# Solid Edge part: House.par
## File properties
Title: House
Author: windows
Template: Iso Metric Part.par
Last saved by: windows
Revision: 7
Application: Solid Edge
Username: windows
Density: 886,000 kg/m^3
Accuracy: 0,990
Material: Polyethylene, low density
Face Style: Blue
Fill Style: ANSI34(Plastic)
Virtual Style: ANSI34(Plastic)
Grouping: Non-metals\Plastics
LibraryName: Materials
Coef. of Thermal Exp: 0.00016
Thermal Conductivity: 3.9
Specific Heat: 2219.0
Modulus of Elasticity: 144789897.0
Poisson's Ratio: 0.35
Yield Stress: 9652659.8
Ultimate Stress: 0.0
Elongation: 0.0
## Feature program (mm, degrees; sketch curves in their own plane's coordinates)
sketch for "unnamed Protrusion 1" plane through (0, 0, 0) normal (0, 0, 1) x-axis (1, 0, 0)
  line (-25, -25) -> (25, -25)
  line (25, -25) -> (25, 25)
  line (25, 25) -> (-25, 25)
  line (-25, 25) -> (-25, -25)
extrude "unnamed Protrusion 1" add finite 50 along +normal
draft "Draft_1"  Angles1 = 10 deg
thinwall "Thinwall_1"  Thickness = 3 mm
chamfer "Chamfer_1" setback 1
sketch for "ExtrudedCutout_1" plane through (0, -20.5918, 25) normal (0, -0.984808, 0.173648) x-axis (1, 0, 0)
  line (12.5, -11.1363) -> (12.5, 13.8637)
  line (12.5, 13.8637) -> (-12.5, 13.8637)
  line (-12.5, 13.8637) -> (-12.5, -11.1363)
  line (-12.5, -11.1363) -> (12.5, -11.1363)
extrude "ExtrudedCutout_1" cut finite 3 along -normal
sketch for "ExtrudedCutout_2" plane through (20.5918, 0, 25) normal (0.984808, 0, 0.173648) x-axis (0, 1, 0)
  line (-12.4342, 5.6895) -> (-2.4342, 5.6895)
  line (-2.4342, 5.6895) -> (-2.4342, 15.6895)
  line (-2.4342, 15.6895) -> (-12.4342, 15.6895)
  line (-12.4342, 15.6895) -> (-12.4342, 5.6895)
extrude "ExtrudedCutout_2" cut finite 3 along -normal
pattern "unnamed Pattern 1" of "ExtrudedCutout_2"
pattern "unnamed Pattern 2"
sketch for "ExtrudedCutout_3" plane through (-20.5918, 0, 25) normal (-0.984808, 0, 0.173648) x-axis (0, -1, 0)
  line (10, 9.4133) -> (-10, 9.4133)
  line (-10, 9.4133) -> (-10, -20.5867)
  line (-10, -20.5867) -> (10, -20.5867)
  line (10, -20.5867) -> (10, 9.4133)
extrude "ExtrudedCutout_3" cut finite 3 along -normal
mirror "unnamed Mirror 1" of "ExtrudedCutout_1"
pattern "unnamed Pattern 3"
sketch for "ExtrudedProtrusion_2" plane through (0, 0, 50) normal (0, 0, 1) x-axis (0, 1, 0)
  line (-35, -35) -> (35, -35)
  line (35, -35) -> (35, 35)
  line (35, 35) -> (-35, 35)
  line (-35, 35) -> (-35, -35)
extrude "ExtrudedProtrusion_2" add finite 40 along +normal
draft "Draft_2"  Angles1 = 40 deg
thinwall "Thinwall_2"  Thickness = 1 mm
sketch for "ExtrudedCutout_4" plane through (0, -18.218, 70) normal (0, -0.766044, 0.642788) x-axis (1, 0, 0)
  line (10, -15.8362) -> (10, 4.1638)
  line (10, 4.1638) -> (-10, 4.1638)
  line (-10, 4.1638) -> (-10, -15.8362)
  line (-10, -15.8362) -> (10, -15.8362)
extrude "ExtrudedCutout_4" cut finite 3 along -normal
fillet "Round_1" radius 5
fillet "Round_2" radius 1
logasc func "Lip_1"  LipOrGrooveWidth = 1.5 mm; LipOrGrooveHeight = 1.5 mm
mirror "unnamed Mirror 2" of "Lip_1" about plane through (0, 0, 0) normal (0, -1, 0)
logasc func "unnamed LOGAscFunc 1"
logasc func "Lip_2"  LipOrGrooveWidth = 1.5 mm; LipOrGrooveHeight = 1.5 mm
logasc func "Lip_3"  LipOrGrooveWidth = 1 mm; LipOrGrooveHeight = 1 mm
logasc func "Lip_4"  LipOrGrooveWidth = 1 mm; LipOrGrooveHeight = 1 mm
logasc func "Lip_5"  LipOrGrooveWidth = 1 mm; LipOrGrooveHeight = 1 mm
logasc func "Lip_6"  LipOrGrooveWidth = 1 mm; LipOrGrooveHeight = 1 mm
logasc func "Lip_7"  LipOrGrooveWidth = 1.5 mm; LipOrGrooveHeight = 1.5 mm
web network "Web_Network_1"  Thickness = 2 mm
draft "Draft_3"  Angles1 = 40 deg
pattern "unnamed Pattern 4" of "ExtrudedCutout_2"
pattern "unnamed Pattern 5"
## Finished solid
Body 1: solid body, 212 faces, 577 edges, 378 vertices.
  Faces by surface: plane 204, cylinder 8
  Edges by curve: line 549, ellipse 28
Bounding box of the edges (mm): 70.000 x 70.000 x 90.000, from (-35, -35, 0) to (35, 35, 90).
Cylindrical faces by radius (mm): R1 x4, R5 x4
Planar faces by outward normal: +x 14, +y 21, +z 5, -x 14, -y 21, -z 5, oblique 124
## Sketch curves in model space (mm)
line (-4.2345, -4.2345, 76) -> (4.2345, -4.2345, 76)
line (-4.2345, 4.2345, 76) -> (4.2345, 4.2345, 76)
line (2.7032, 2.7032, 76) -> (2.7032, -2.7032, 76)
line (-2.7032, 2.7032, 76) -> (-2.7032, -2.7032, 76)
line (10, -28.3973, 57.8688) -> (10, -15.5415, 73.1897)
line (10, -15.5415, 73.1897) -> (-10, -15.5415, 73.1897)
line (-10, -15.5415, 73.1897) -> (-10, -28.3973, 57.8688)
line (-10, -28.3973, 57.8688) -> (10, -28.3973, 57.8688)
line (-24.1667, -10, 4.7261) -> (-18.9572, -10, 34.2703)
line (-18.9572, -10, 34.2703) -> (-18.9572, 10, 34.2703)
line (-18.9572, 10, 34.2703) -> (-24.1667, 10, 4.7261)
line (-24.1667, 10, 4.7261) -> (-24.1667, -10, 4.7261)
line (19.6039, -2.4342, 30.603) -> (17.8674, -2.4342, 40.4511)
line (17.8674, -2.4342, 40.4511) -> (17.8674, -12.4342, 40.4511)
line (17.8674, -12.4342, 40.4511) -> (19.6039, -12.4342, 30.603)
line (19.6039, -12.4342, 30.603) -> (19.6039, -2.4342, 30.603)
line (12.5, -22.5256, 14.0329) -> (12.5, -18.1844, 38.6531)
line (12.5, -18.1844, 38.6531) -> (-12.5, -18.1844, 38.6531)
line (-12.5, -18.1844, 38.6531) -> (-12.5, -22.5256, 14.0329)
line (-12.5, -22.5256, 14.0329) -> (12.5, -22.5256, 14.0329)
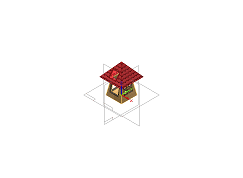
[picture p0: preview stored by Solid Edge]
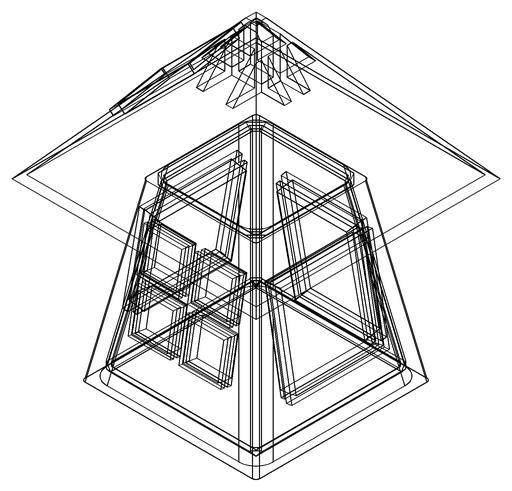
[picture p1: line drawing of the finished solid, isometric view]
